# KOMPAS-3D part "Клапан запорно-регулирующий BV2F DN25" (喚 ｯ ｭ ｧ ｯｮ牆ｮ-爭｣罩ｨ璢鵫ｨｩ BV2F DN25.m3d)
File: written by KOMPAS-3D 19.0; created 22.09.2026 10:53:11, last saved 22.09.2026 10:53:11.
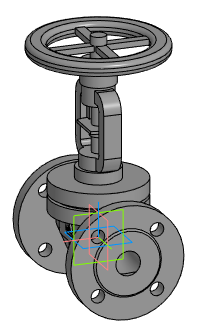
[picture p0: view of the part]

Document properties: Автор: Энергия; Полное имя файла: Z:\3.Личные\sachek\Dendor\_3D для проектировщиков\5.7 Клапан запорно-регулирующий BV2F\BV2F_STP\Клапан запорно-регулирующий BV2F DN25.m3d

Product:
- Part/product: Клапан запорно-регулирующий BV2F DN25

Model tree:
1. Операция без истории:1  (labels: Клапан запорно-регулирующий BV2F DN25)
